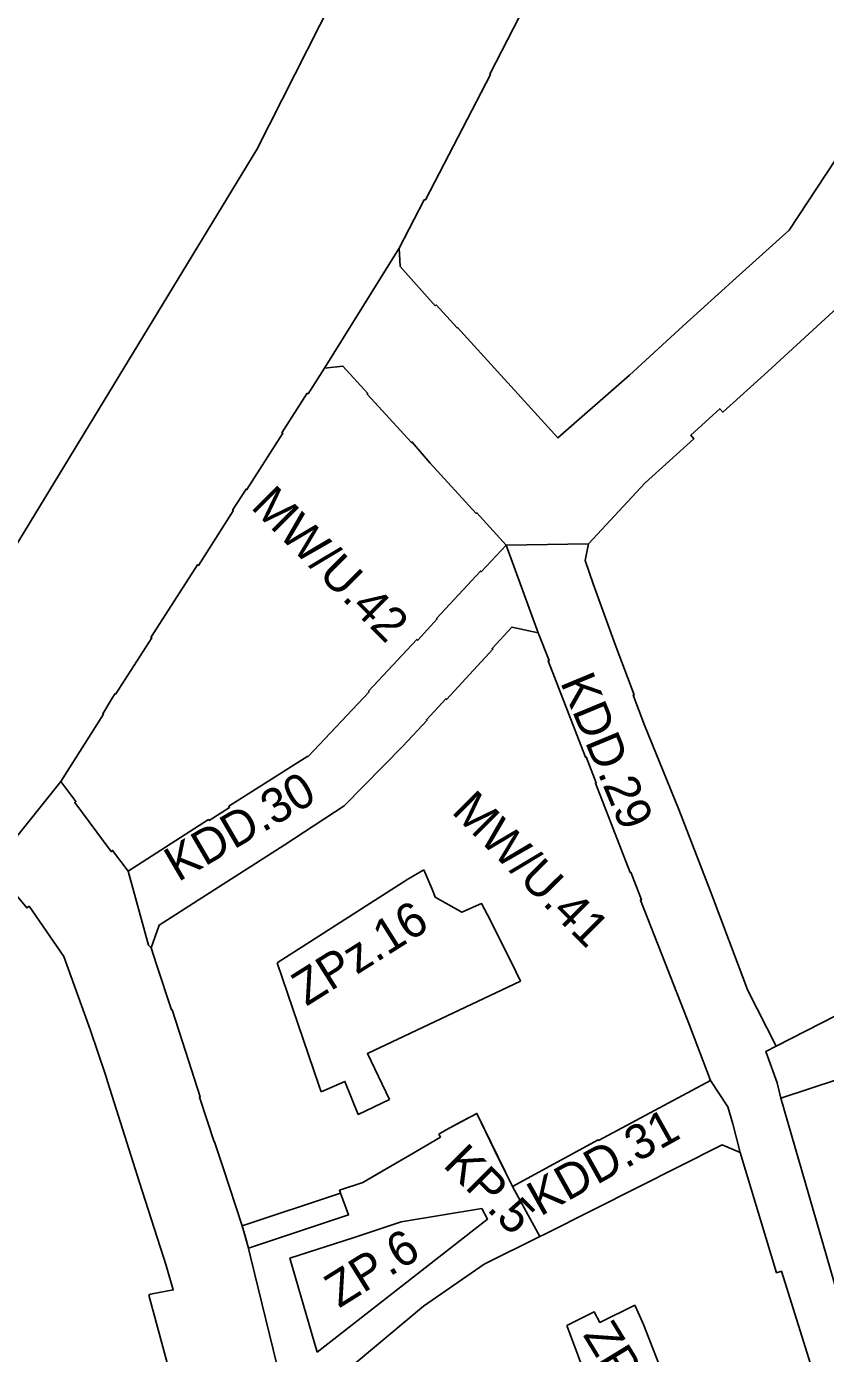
# Model space of a CAD drawing. Extents: x 7423835 to 7425280, y 5546086 to 5547600.
# Drawn here: x 7424227.3 to 7424365.2, y 5546605 to 5546834 of the extents above; entities that cross this region are included whole.
import ezdxf

# ---------------------------------------------------------------- set-up
doc = ezdxf.new("R2010")
doc.units = 0
for name, color, linetype in [('linie rozgraniczające', 7, 'Continuous'), ('nieprzekraczalne linie zabudowy', 7, 'Continuous'), ('obowiazujace linie zabudowy', 7, 'Continuous'), ('przeznaczenia terenów', 7, 'Continuous')]:
    doc.layers.add(name, color=color, linetype=linetype)

msp = doc.modelspace()

# ---------------------------------------------------------------- linework, layer by layer
at = {"layer": 'linie rozgraniczające'}
for p, q in [((7424291.6, 5546795.75), (7424278.72, 5546775.08)), ((7424310.09, 5546744.51), (7424324.29, 5546744.76)), ((7424310.09, 5546744.51), (7424315.62, 5546729.4)), ((7424233.24, 5546703.71), (7424220.01, 5546687.22)), ((7424357.5, 5546649.05), (7424356.85, 5546651.75)), ((7424311.17, 5546633.83), (7424315.91, 5546625.2)), ((7424277.46, 5546605.25), (7424306.87, 5546628.21)), ((7424283.87, 5546625.05), (7424272.74, 5546621.44)), ((7424272.74, 5546621.44), (7424277.46, 5546605.25)), ((7424320.53, 5546609.85), (7424325.27, 5546597.26))]:
    msp.add_line(p, q, dxfattribs=at)
for points in [[(7424213.38, 5546724.52), (7424267.06, 5546812.79), (7424421.63, 5547117.9)], [(7424321.42, 5546853.23), (7424311.33, 5546833.75), (7424307.26, 5546825.79), (7424307.38, 5546825.72), (7424296.17, 5546804.11), (7424295.94, 5546804.08), (7424291.6, 5546795.75)], [(7424291.6, 5546795.75), (7424291.81, 5546792.57), (7424297.85, 5546785.83), (7424298.01, 5546785.97), (7424301.66, 5546782.01), (7424301.72, 5546782.05), (7424319.01, 5546763.01), (7424331.35, 5546773.85), (7424340.6, 5546782.3), (7424349.73, 5546790.56), (7424358.93, 5546798.87), (7424366.91, 5546810.99), (7424378.18, 5546828.24), (7424386.41, 5546841.23)], [(7424367.92, 5546786.13), (7424355.21, 5546774.47), (7424347.48, 5546767.46), (7424346.94, 5546768.06), (7424341.95, 5546763.48), (7424342.47, 5546762.86), (7424334.06, 5546755.28), (7424324.29, 5546744.76), (7424323.73, 5546741.84), (7424325.08, 5546737.86), (7424328.92, 5546727.35), (7424332.17, 5546718.68), (7424332.03, 5546718.63), (7424333.98, 5546713.44), (7424339.91, 5546698.91), (7424345.29, 5546684.9), (7424351.77, 5546667.63), (7424356.67, 5546658.07), (7424377.38, 5546668.63)], [(7424310.09, 5546744.51), (7424305.03, 5546750.09), (7424304.91, 5546749.98), (7424296.98, 5546758.66), (7424293.88, 5546762.29), (7424293.76, 5546762.2), (7424286.1, 5546770.58), (7424286.22, 5546770.69), (7424281.92, 5546775.42), (7424278.72, 5546775.08), (7424275.92, 5546770.62), (7424275.77, 5546770.72), (7424271.41, 5546763.92), (7424271.57, 5546763.82), (7424265.35, 5546754.09), (7424265.21, 5546754.18), (7424262.89, 5546750.56), (7424263, 5546750.46), (7424257.01, 5546741.02), (7424256.85, 5546741.13), (7424248.78, 5546728.59), (7424248.94, 5546728.49), (7424242.76, 5546718.84), (7424242.64, 5546718.91), (7424242.12, 5546718.08), (7424240.47, 5546715.42), (7424240.61, 5546715.33), (7424233.24, 5546703.71)], [(7424310.09, 5546744.51), (7424305.79, 5546739.93), (7424305.68, 5546740.04), (7424298.09, 5546731.88), (7424298.2, 5546731.79), (7424294.82, 5546728.11), (7424294.68, 5546728.24), (7424286.34, 5546719.29), (7424286.44, 5546719.17), (7424275.91, 5546708.04), (7424275.84, 5546708.09), (7424262.23, 5546699.45), (7424262.37, 5546699.24), (7424258.86, 5546696.97), (7424258.74, 5546697.14), (7424244.87, 5546688.27), (7424242.18, 5546691.84), (7424241.92, 5546691.64), (7424235.65, 5546700.11), (7424235.84, 5546700.25), (7424233.24, 5546703.71)], [(7424311.17, 5546633.83), (7424325.96, 5546641.89), (7424326.01, 5546641.8), (7424345.36, 5546652.1), (7424341.73, 5546661.65), (7424337.44, 5546672.56), (7424333.26, 5546683.25), (7424333.44, 5546683.32), (7424331.59, 5546688.05), (7424331.46, 5546688), (7424325.48, 5546703.44), (7424325.63, 5546703.49), (7424323.9, 5546707.96), (7424323.76, 5546707.91), (7424317.32, 5546724.52), (7424317.48, 5546724.58), (7424315.62, 5546729.4), (7424311.06, 5546730.35), (7424307.66, 5546726.69), (7424307.79, 5546726.57), (7424299.8, 5546717.87), (7424299.66, 5546718), (7424296.33, 5546714.38), (7424296.44, 5546714.28), (7424292.27, 5546709.8), (7424282.15, 5546699.51), (7424271.77, 5546692.73), (7424259.83, 5546685.11), (7424250.19, 5546678.94), (7424248.83, 5546675.03)], [(7424253.09, 5546597.9), (7424248.43, 5546615.1), (7424248.72, 5546615.23), (7424252.65, 5546616), (7424251.4, 5546620.2), (7424246.8, 5546634.55), (7424241.34, 5546651.77), (7424240.95, 5546653.11), (7424238.34, 5546660.94), (7424238.09, 5546661.56), (7424233.76, 5546673.51), (7424227.76, 5546682.21), (7424227.37, 5546681.92), (7424224.28, 5546685.65), (7424222.66, 5546687.33), (7424220.01, 5546687.22)], [(7424244.87, 5546688.27), (7424248.35, 5546675.47), (7424248.83, 5546675.03)], [(7424295.88, 5546688.46), (7424293.13, 5546686.87), (7424270.55, 5546672.42)], [(7424295.88, 5546688.46), (7424297.41, 5546684.84), (7424297.85, 5546683.79)], [(7424289.98, 5546648.83), (7424286.15, 5546656.81), (7424312.55, 5546669.27), (7424311.76, 5546670.93), (7424307.39, 5546679.75), (7424305.86, 5546682.66), (7424302.45, 5546681.15), (7424297.85, 5546683.79)], [(7424415.44, 5546675.99), (7424420.93, 5546660.04), (7424421.75, 5546657.53), (7424423.79, 5546651.25), (7424427.88, 5546638.9), (7424441.46, 5546599.12), (7424429.54, 5546594.89), (7424419.97, 5546592.1), (7424408.6, 5546588.75), (7424395.96, 5546584.68), (7424377.65, 5546579.36), (7424357.5, 5546649.05), (7424367.44, 5546652.38), (7424372.88, 5546654.73), (7424377.74, 5546656.83), (7424384.62, 5546660.5)], [(7424248.83, 5546675.03), (7424249.78, 5546672.14), (7424252.34, 5546664.3), (7424252.48, 5546664.35), (7424254.78, 5546657.18), (7424257.3, 5546649.3), (7424257.17, 5546649.26), (7424259.68, 5546641.55), (7424259.78, 5546641.57), (7424261.26, 5546637.03), (7424264.54, 5546627.07)], [(7424270.55, 5546672.42), (7424277.76, 5546651.32), (7424278.15, 5546650.18)], [(7424356.67, 5546658.07), (7424354.91, 5546657.15), (7424356.85, 5546651.75)], [(7424289.98, 5546648.83), (7424284.56, 5546646.26), (7424282.27, 5546651.98), (7424278.15, 5546650.18)], [(7424345.36, 5546652.1), (7424348.36, 5546647.57), (7424349.21, 5546644.63), (7424350.47, 5546639.68)], [(7424264.54, 5546627.07), (7424281.53, 5546632.7), (7424281.34, 5546633.22), (7424285.38, 5546634.53), (7424293.45, 5546639.24), (7424293.48, 5546639.26), (7424298.78, 5546642.37), (7424298.49, 5546642.86), (7424299.71, 5546643.62), (7424305.03, 5546646.44), (7424311.17, 5546633.83)], [(7424281.07, 5546600.81), (7424295.83, 5546613.18), (7424306.31, 5546620.41), (7424315.91, 5546625.2), (7424316.64, 5546625.56), (7424325.19, 5546629.87), (7424347.37, 5546641.01), (7424350.47, 5546639.68), (7424356.76, 5546618.96), (7424357.59, 5546619.22), (7424363.45, 5546600.46)], [(7424305.9, 5546630.01), (7424291.99, 5546627.74), (7424283.87, 5546625.05)], [(7424305.9, 5546630.01), (7424306.87, 5546628.21), (7424306.87, 5546628.21)], [(7424264.54, 5546627.07), (7424265.35, 5546624.27), (7424271.84, 5546597.69), (7424273.24, 5546594.48)], [(7424332.31, 5546613.36), (7424326.23, 5546610.37), (7424325.27, 5546612.22), (7424320.53, 5546609.85)], [(7424332.31, 5546613.36), (7424332.85, 5546612.12), (7424333.77, 5546610), (7424337.62, 5546600.12), (7424340.73, 5546592.1)]]:
    msp.add_lwpolyline(points, dxfattribs=at)
at = {"layer": 'nieprzekraczalne linie zabudowy'}
msp.add_lwpolyline([(7424264.54, 5546627.07), (7424265.65, 5546623.22), (7424282.9, 5546628.94), (7424281.53, 5546632.7)], dxfattribs=at)
at = {"layer": 'obowiazujace linie zabudowy'}
for points in [[(7424321.42, 5546853.23), (7424311.33, 5546833.75), (7424307.26, 5546825.79), (7424307.38, 5546825.72), (7424296.17, 5546804.11), (7424295.94, 5546804.08), (7424291.6, 5546795.75)], [(7424291.6, 5546795.75), (7424291.81, 5546792.57), (7424297.85, 5546785.83), (7424298.01, 5546785.97), (7424301.66, 5546782.01), (7424301.72, 5546782.05), (7424319.01, 5546763.01), (7424331.35, 5546773.85), (7424340.6, 5546782.3), (7424349.73, 5546790.56), (7424358.93, 5546798.87), (7424366.91, 5546810.99), (7424378.18, 5546828.24), (7424386.41, 5546841.23)], [(7424367.92, 5546786.13), (7424355.21, 5546774.47), (7424347.48, 5546767.46), (7424346.94, 5546768.06), (7424341.95, 5546763.48), (7424342.47, 5546762.86), (7424334.06, 5546755.28), (7424324.29, 5546744.76), (7424323.73, 5546741.84), (7424325.08, 5546737.86), (7424328.92, 5546727.35), (7424332.17, 5546718.68), (7424332.03, 5546718.63), (7424333.98, 5546713.44), (7424339.91, 5546698.91), (7424345.29, 5546684.9), (7424351.77, 5546667.63), (7424356.67, 5546658.07), (7424377.38, 5546668.63)], [(7424310.09, 5546744.51), (7424305.03, 5546750.09), (7424304.91, 5546749.98), (7424296.98, 5546758.66), (7424293.88, 5546762.29), (7424293.76, 5546762.2), (7424286.1, 5546770.58), (7424286.22, 5546770.69), (7424281.92, 5546775.42), (7424278.72, 5546775.08), (7424275.92, 5546770.62), (7424275.77, 5546770.72), (7424271.41, 5546763.92), (7424271.57, 5546763.82), (7424265.35, 5546754.09), (7424265.21, 5546754.18), (7424262.89, 5546750.56), (7424263, 5546750.46), (7424257.01, 5546741.02), (7424256.85, 5546741.13), (7424248.78, 5546728.59), (7424248.94, 5546728.49), (7424242.76, 5546718.84), (7424242.64, 5546718.91), (7424242.12, 5546718.08), (7424240.47, 5546715.42), (7424240.61, 5546715.33), (7424233.24, 5546703.71)], [(7424233.24, 5546703.71), (7424235.84, 5546700.25), (7424235.65, 5546700.11), (7424241.92, 5546691.64), (7424242.18, 5546691.84), (7424244.87, 5546688.27), (7424258.74, 5546697.14), (7424258.86, 5546696.97), (7424262.37, 5546699.24), (7424262.23, 5546699.45), (7424275.84, 5546708.09), (7424275.91, 5546708.04), (7424286.44, 5546719.17), (7424286.34, 5546719.29), (7424294.68, 5546728.24), (7424294.82, 5546728.11), (7424298.2, 5546731.79), (7424298.09, 5546731.88), (7424305.68, 5546740.04), (7424305.79, 5546739.93), (7424310.09, 5546744.51)], [(7424311.17, 5546633.83), (7424325.96, 5546641.89), (7424326.01, 5546641.8), (7424345.36, 5546652.1), (7424341.73, 5546661.65), (7424337.44, 5546672.56), (7424333.26, 5546683.25), (7424333.44, 5546683.32), (7424331.59, 5546688.05), (7424331.46, 5546688), (7424325.48, 5546703.44), (7424325.63, 5546703.49), (7424323.9, 5546707.96), (7424323.76, 5546707.91), (7424317.32, 5546724.52), (7424317.48, 5546724.58), (7424315.62, 5546729.4), (7424311.06, 5546730.35), (7424307.66, 5546726.69), (7424307.79, 5546726.57), (7424299.8, 5546717.87), (7424299.66, 5546718), (7424296.33, 5546714.38), (7424296.44, 5546714.28), (7424292.27, 5546709.8), (7424282.15, 5546699.51), (7424271.77, 5546692.73), (7424259.83, 5546685.11), (7424250.19, 5546678.94), (7424248.83, 5546675.03)], [(7424253.09, 5546597.9), (7424248.43, 5546615.1), (7424248.72, 5546615.23), (7424252.65, 5546616), (7424251.4, 5546620.2), (7424246.8, 5546634.55), (7424241.34, 5546651.77), (7424240.95, 5546653.11), (7424238.34, 5546660.94), (7424238.09, 5546661.56), (7424233.76, 5546673.51), (7424227.76, 5546682.21), (7424227.37, 5546681.92), (7424224.28, 5546685.65), (7424222.66, 5546687.33), (7424220.01, 5546687.22)], [(7424248.83, 5546675.03), (7424249.78, 5546672.14), (7424252.34, 5546664.3), (7424252.48, 5546664.35), (7424254.78, 5546657.18), (7424257.3, 5546649.3), (7424257.17, 5546649.26), (7424259.68, 5546641.55), (7424259.78, 5546641.57), (7424261.26, 5546637.03), (7424264.54, 5546627.07)], [(7424367.44, 5546652.38), (7424357.5, 5546649.05), (7424377.65, 5546579.36), (7424395.96, 5546584.68), (7424408.6, 5546588.75), (7424419.97, 5546592.1), (7424429.54, 5546594.89), (7424441.46, 5546599.12), (7424427.88, 5546638.9), (7424421.71, 5546657.52)], [(7424281.53, 5546632.7), (7424281.34, 5546633.22), (7424285.38, 5546634.53), (7424289.41, 5546636.89), (7424293.45, 5546639.24), (7424296.13, 5546640.82), (7424298.78, 5546642.37), (7424298.49, 5546642.86), (7424299.71, 5546643.62), (7424302.37, 5546645.03), (7424305.03, 5546646.44), (7424308.1, 5546640.13), (7424311.17, 5546633.83)], [(7424363.45, 5546600.46), (7424357.59, 5546619.22), (7424356.76, 5546618.96), (7424350.47, 5546639.68), (7424347.37, 5546641.01), (7424325.19, 5546629.87), (7424316.64, 5546625.56), (7424315.91, 5546625.2), (7424306.31, 5546620.41), (7424295.83, 5546613.18), (7424281.07, 5546600.81)]]:
    msp.add_lwpolyline(points, dxfattribs=at)

# ---------------------------------------------------------------- texts
at = {"layer": 'przeznaczenia terenów'}
for s, rotation, p in [('MW/U.42', 314.9764, (7424265.85, 5546750.99)), ('KDD.29', 292.5464, (7424319.35, 5546720.88)), ('KDD.30', 30.3163, (7424253.47, 5546686.31)), ('MW/U.41', 314.9764, (7424300.48, 5546698.39)), ('ZPz.16', 32.173, (7424275.61, 5546664.86)), ('KDD.31', 29.1907, (7424315.96, 5546628.61)), ('KP.5', 314.9764, (7424299.03, 5546637.41)), ('ZP.6', 31.9858, (7424281.26, 5546612.77)), ('ZPz.17', 301.4234, (7424323.24, 5546608.23))]:
    msp.add_text(s, height=6, rotation=rotation, dxfattribs=at).set_placement(p)

doc.saveas('drawing.dxf')
